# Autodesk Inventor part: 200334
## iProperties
Created: 2007-12
Part Number: 200334
Document SubType Name: Modeling
Designer: MM
Density: 7.85 g/cm^3
Mass: 20.5196 g
Surface Area: 22.5328 cm^2
Volume: 2.61396 cm^3
Material: Steel
Description: SPACER
Component Category: Lower Component
Author: MM
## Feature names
1. Extrusion1
